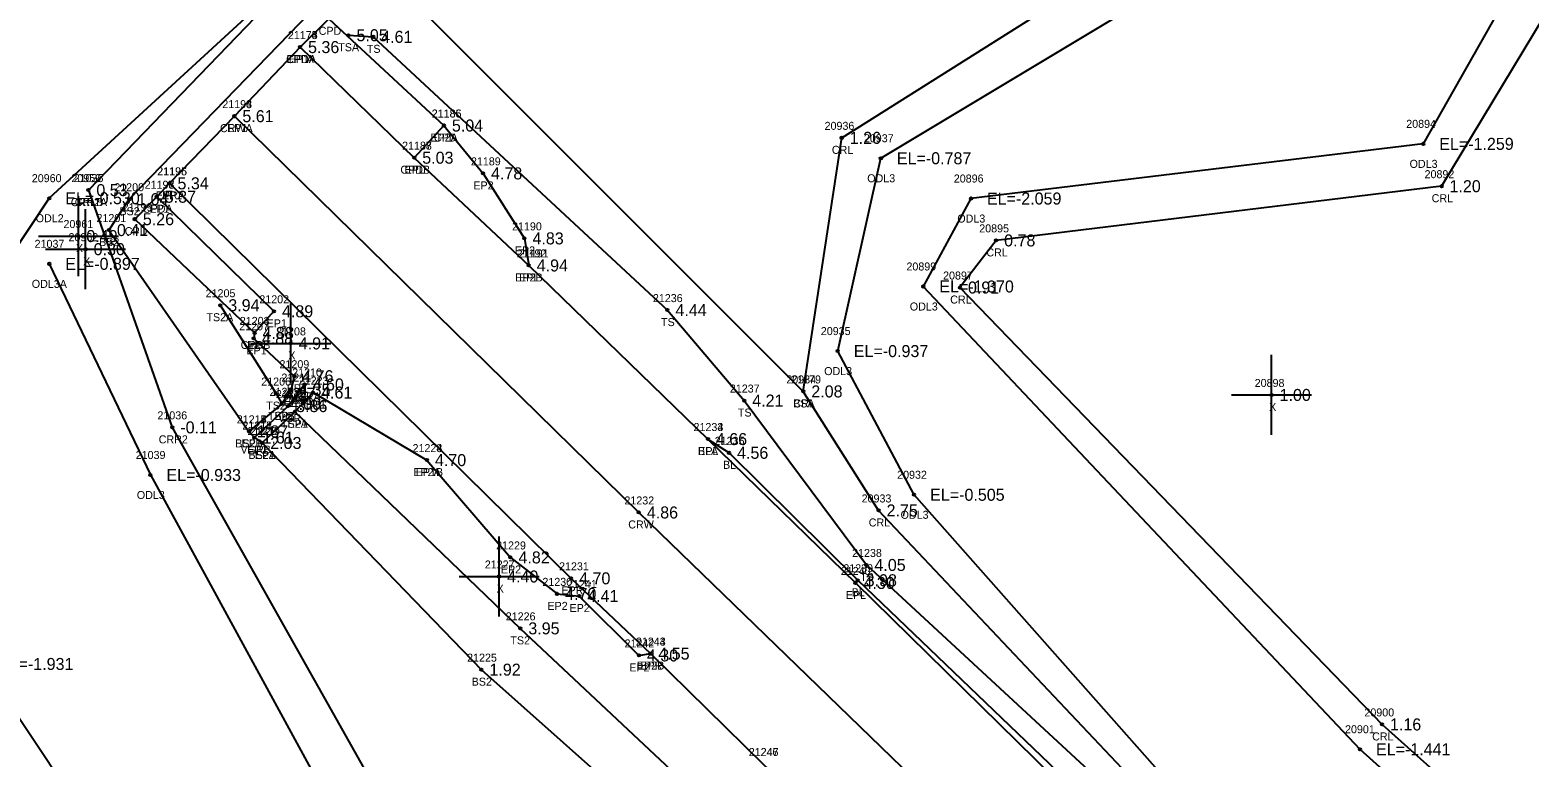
# Model space of a CAD drawing. Extents: x 2608745 to 2610333, y 641917 to 643463.
# Drawn here: x 2609542.9 to 2609730.2, y 642567.4 to 642658.2 of the extents above; entities that cross this region are included whole.
import ezdxf

# ---------------------------------------------------------------- set-up
doc = ezdxf.new("R2010")
doc.units = 0
for name, color, linetype in [('RD_DTM_BkLn1', 7, 'Continuous'), ('RD_DTM_BkLn2', 7, 'Continuous'), ('RD_DTM_BkLn_txCode', 7, 'Continuous'), ('RD_EX_Conc', 7, 'Continuous'), ('RD_EX_Conc_txCode', 7, 'Continuous'), ('RD_EX_H2O', 7, 'Continuous'), ('RD_EX_H2O_txCode', 7, 'Continuous'), ('RD_EX_Misc', 7, 'Continuous'), ('RD_EX_Misc_txCode', 7, 'Continuous'), ('RD_EX_Road', 7, 'Continuous'), ('RD_EX_Road_txCode', 7, 'Continuous'), ('RD_EX_TX_Conc_ELEV', 7, 'Continuous'), ('RD_EX_TX_H2O_ELEV', 7, 'Continuous'), ('RD_EX_TX_Misc_ELEV', 7, 'Continuous'), ('RD_EX_TX_Road_ELEV', 7, 'Continuous'), ('RD_HC_Survey_ELEV', 7, 'Continuous'), ('RD_HC_Survey_txCode', 7, 'Continuous'), ('RD_SMD_Locator', 7, 'Continuous')]:
    doc.layers.add(name, color=color, linetype=linetype)

msp = doc.modelspace()

# ---------------------------------------------------------------- linework, layer by layer
at = {"layer": 'RD_DTM_BkLn1'}
for points in [[(2609568.4, 642647.43), (2609618.95, 642597.92), (2609693.89, 642525.38), (2609771.33, 642450.27), (2609850.26, 642373.69), (2609929.54, 642297.24), (2610000.01, 642230.49), (2610078.71, 642154.75), (2610156.09, 642080.44), (2610235.53, 642002.94), (2610263.59, 641975.77)], [(2609627.58, 642607.09), (2609630.23, 642605.37), (2609646.31, 642589.45), (2609703.16, 642535.02), (2609781.51, 642459.84), (2609859.44, 642383.51), (2609938.95, 642307.03), (2610008.76, 642239.49), (2610086.74, 642162.99), (2610105.31, 642145.89), (2610105.31, 642145.89), (2610140.26, 642113.1), (2610153.89, 642100.28), (2610164.72, 642089.82), (2610189.2, 642065.46)]]:
    msp.add_lwpolyline(points, dxfattribs=at)
at = {"layer": 'RD_DTM_BkLn2'}
msp.add_line((2609639.51, 642613.04), (2609586.16, 642666.36), dxfattribs=at)
for points in [[(2609586.16, 642666.36), (2609582.27, 642665.19), (2609577.87, 642660.38), (2609555.26, 642637.05), (2609552.72, 642633.2), (2609570.22, 642608.05)], [(2609582.66, 642657.54), (2609585.75, 642657.34), (2609622.53, 642623.2), (2609632.13, 642611.9), (2609647.4, 642591.36), (2609682.93, 642558.52), (2609706.14, 642537.77), (2609755.54, 642496.98), (2609786.05, 642464.88), (2609864.24, 642388.44), (2609941.53, 642310.67), (2610012.94, 642244.46), (2610082.83, 642179.18), (2610093.52, 642170.29)], [(2609566.64, 642623.81), (2609573.62, 642612.77), (2609574.32, 642611.49)], [(2609575.96, 642610.5), (2609604.14, 642583.44), (2609629.67, 642559.46), (2609643.02, 642545.36), (2609646.06, 642538.31)], [(2609571.88, 642606.6), (2609599.28, 642578.28), (2609624.62, 642555.74), (2609639.66, 642545.5), (2609646.06, 642538.31)]]:
    msp.add_lwpolyline(points, dxfattribs=at)
at = {"layer": 'RD_EX_Conc'}
for points in [[(2609576.61, 642656.06), (2609580.19, 642659.59), (2609594.59, 642646.26), (2609590.88, 642642.24)], [(2609558.7, 642637.36), (2609555.96, 642634.56), (2609570.92, 642620.35)]]:
    msp.add_lwpolyline(points, dxfattribs=at)
at = {"layer": 'RD_EX_H2O'}
for points in [[(2609940.72, 642981.52), (2609865.8, 642912.86), (2609792.29, 642852.87), (2609723.77, 642786.36), (2609663.25, 642717.18), (2609610.37, 642689.46), (2609581.45, 642670.47), (2609545.26, 642637.18), (2609509.19, 642582.86), (2609482.73, 642569.2), (2609408.72, 642506.3), (2609370.25, 642508.5), (2609327.7, 642455.81), (2609283.83, 642369.21), (2609262.12, 642251.22)], [(2609943.79, 642976.05), (2609869.55, 642907.14), (2609797.73, 642847.7), (2609725.24, 642780.75), (2609667.97, 642714.2), (2609673.28, 642700.22), (2609713.56, 642689.91), (2609733.33, 642661.98), (2609719.28, 642638.68), (2609663.61, 642631.91), (2609659.09, 642626.02), (2609711.84, 642571.44), (2609760.21, 642528.21), (2609792.62, 642516.23), (2609800.76, 642528.12), (2609797.45, 642563.99), (2609816.12, 642605.87)], [(2609662.06, 642711.74), (2609667.71, 642698.47), (2609710.28, 642682.9), (2609727.91, 642663.26), (2609716.99, 642643.97), (2609660.46, 642637.14), (2609654.51, 642626.15), (2609709.09, 642568.34), (2609756.97, 642525.37), (2609791.92, 642510.53), (2609803.29, 642524.08), (2609799.58, 642559.74), (2609817.68, 642600.07)], [(2609827.02, 642593.77), (2609813.83, 642563.83), (2609821.87, 642523.17), (2609816.05, 642503.71), (2609776.93, 642503.96), (2609742.39, 642528.68), (2609685.39, 642563.92), (2609653.36, 642600.13), (2609643.82, 642618.08), (2609649.2, 642642.17), (2609682.55, 642662.2), (2609681.94, 642669.7), (2609650.34, 642688.25), (2609625.49, 642693.15)], [(2609830.46, 642590.52), (2609816.18, 642559.99), (2609824.93, 642525.1), (2609819.57, 642500.66), (2609777.53, 642499.54), (2609740.45, 642527.35), (2609685.03, 642559.92), (2609648.92, 642598.17), (2609639.51, 642613.04), (2609644.31, 642644.72), (2609677.66, 642665.76), (2609646.17, 642685.39), (2609611.73, 642684.8), (2609586.16, 642666.36), (2609575.62, 642664.58), (2609550.15, 642638.19)], [(2609550.15, 642638.19), (2609560.64, 642608.55), (2609596.58, 642544.67), (2609665.26, 642493.63), (2609726.89, 642435.57), (2609728.97, 642442.01), (2609745.88, 642433.78), (2609753.45, 642414.77), (2609764.24, 642411.87), (2609765.65, 642391.82), (2609764.35, 642384.35), (2609816.5, 642340.65), (2609898.67, 642278.63), (2609932.36, 642236.09), (2609918.8, 642192.33)], [(2609545.26, 642628.98), (2609557.91, 642602.6), (2609591.74, 642540.6), (2609658.48, 642494.06), (2609739.9, 642422.86), (2609760.07, 642378.85), (2609808.54, 642339.07), (2609896.37, 642269.89), (2609925.48, 642240.69), (2609915.11, 642188.91), (2609891.33, 642158.21), (2609835.84, 642063.03)], [(2609518.22, 642586.65), (2609536.97, 642578.99), (2609575.62, 642520.95), (2609643.94, 642461.12), (2609713.29, 642393.38), (2609797.14, 642314.29), (2609845.08, 642297.38), (2609901.61, 642240.2), (2609849.12, 642177.48), (2609793.89, 642090.6)]]:
    msp.add_lwpolyline(points, dxfattribs=at)
at = {"layer": 'RD_EX_Misc'}
for p, q in [((2609548.9, 642627.45), (2609548.9, 642637.45)), ((2609549.81, 642625.81), (2609549.81, 642635.81)), ((2609543.9, 642632.45), (2609553.9, 642632.45)), ((2609544.81, 642630.81), (2609554.81, 642630.81)), ((2609575.45, 642614.04), (2609575.45, 642624.04)), ((2609570.45, 642619.04), (2609580.45, 642619.04)), ((2609698.04, 642607.6), (2609698.04, 642617.6)), ((2609693.04, 642612.6), (2609703.04, 642612.6)), ((2609601.49, 642584.92), (2609601.49, 642594.92)), ((2609596.49, 642589.92), (2609606.49, 642589.92))]:
    msp.add_line(p, q, dxfattribs=at)
at = {"layer": 'RD_EX_Road'}
for points in [[(2609576.61, 642656.06), (2609568.4, 642647.43), (2609560.29, 642639.04), (2609558.7, 642637.36), (2609573.35, 642623.05), (2609570.92, 642620.35), (2609570.83, 642619.67), (2609575.88, 642614.94), (2609575.51, 642613.27), (2609574.32, 642611.49), (2609570.22, 642608.05), (2609570.91, 642607.28), (2609571.88, 642606.6), (2609575.96, 642610.5), (2609578.24, 642612.9), (2609592.47, 642604.46)], [(2609576.61, 642656.06), (2609590.88, 642642.24), (2609605.19, 642628.78), (2609627.58, 642607.09), (2609646.03, 642589.11), (2609702.18, 642534.04), (2609780.35, 642458.95), (2609858.79, 642382.83), (2609938.32, 642306.42), (2610008.62, 642239.32), (2610086.3, 642162.54), (2610164.18, 642089.49), (2610189.2, 642065.46), (2610214.78, 642040.19), (2610225.86, 642030.16), (2610226.32, 642028.39), (2610235.43, 642019.75), (2610260.23, 641995.63), (2610272.39, 641983.25)], [(2609594.59, 642646.26), (2609599.48, 642640.28), (2609604.66, 642632.16), (2609605.19, 642628.78)], [(2609560.29, 642639.04), (2609610.49, 642589.69), (2609620.39, 642580.29), (2609634.49, 642566.49), (2609647.6, 642554.19), (2609656.49, 642545.43), (2609683.33, 642519.48), (2609697.84, 642505.38), (2609722.29, 642481.47), (2609722.29, 642481.47), (2609722.29, 642481.47), (2609762.93, 642442.03), (2609781.47, 642423.77), (2609797.04, 642408.62), (2609841.8, 642365.54), (2609898.22, 642311.07)], [(2609577.18, 642613.91), (2609575.12, 642611.21), (2609570.91, 642607.28)], [(2609592.47, 642604.46), (2609602.91, 642592.3), (2609608.74, 642587.75), (2609611.5, 642587.48), (2609618.96, 642580.06), (2609620.39, 642580.29)]]:
    msp.add_lwpolyline(points, dxfattribs=at)
at = {"layer": 'RD_SMD_Locator'}
for centre in [(2609582.66, 642657.54), (2609585.75, 642657.34), (2609576.61, 642656.06), (2609576.61, 642656.06), (2609576.61, 642656.06), (2609568.4, 642647.43), (2609568.4, 642647.43), (2609594.59, 642646.26), (2609594.59, 642646.26), (2609644.31, 642644.72), (2609716.99, 642643.97), (2609590.88, 642642.24), (2609590.88, 642642.24), (2609649.2, 642642.17), (2609599.48, 642640.28), (2609550.15, 642638.19), (2609550.15, 642638.19), (2609560.29, 642639.04), (2609560.29, 642639.04), (2609719.28, 642638.68), (2609545.26, 642637.18), (2609555.26, 642637.05), (2609558.7, 642637.36), (2609558.7, 642637.36), (2609660.46, 642637.14), (2609555.96, 642634.56), (2609552.72, 642633.2), (2609548.9, 642632.45), (2609549.81, 642630.81), (2609604.66, 642632.16), (2609663.61, 642631.91), (2609545.26, 642628.98), (2609605.19, 642628.78), (2609605.19, 642628.78), (2609654.51, 642626.15), (2609659.09, 642626.02), (2609566.64, 642623.81), (2609622.53, 642623.2), (2609573.35, 642623.05), (2609570.83, 642619.67), (2609570.92, 642620.35), (2609570.92, 642620.35), (2609575.45, 642619.04), (2609643.82, 642618.08), (2609575.88, 642614.94), (2609577.18, 642613.91), (2609573.62, 642612.77), (2609575.51, 642613.27), (2609578.24, 642612.9), (2609639.51, 642613.04), (2609639.51, 642613.04), (2609698.04, 642612.6), (2609574.32, 642611.49), (2609574.32, 642611.49), (2609575.12, 642611.21), (2609575.96, 642610.5), (2609575.96, 642610.5), (2609632.13, 642611.9), (2609560.64, 642608.55), (2609570.22, 642608.05), (2609570.22, 642608.05), (2609570.91, 642607.28), (2609570.91, 642607.28), (2609571.88, 642606.6), (2609571.88, 642606.6), (2609627.58, 642607.09), (2609627.58, 642607.09), (2609592.47, 642604.46), (2609592.47, 642604.46), (2609630.23, 642605.37), (2609557.91, 642602.6), (2609653.36, 642600.13), (2609618.95, 642597.92), (2609648.92, 642598.17), (2609602.91, 642592.3), (2609647.4, 642591.36), (2609601.49, 642589.92), (2609610.49, 642589.69), (2609608.74, 642587.75), (2609646.03, 642589.11), (2609646.31, 642589.45), (2609611.5, 642587.48), (2609604.14, 642583.44), (2609620.39, 642580.29), (2609620.39, 642580.29), (2609599.28, 642578.28), (2609618.96, 642580.06), (2609711.84, 642571.44), (2609709.09, 642568.34)]:
    msp.add_circle(centre, 0.15, dxfattribs=at)

# ---------------------------------------------------------------- texts
at = {"layer": 'RD_DTM_BkLn_txCode'}
for s, p in [('TSA', (2609581.38, 642655.54)), ('TS', (2609584.95, 642655.34)), ('21200', (2609553.39, 642638.05)), ('21201', (2609551.17, 642634.2)), ('BS2', (2609554.03, 642635.05)), ('BS2', (2609551.49, 642631.2)), ('21205', (2609564.81, 642624.81)), ('21236', (2609620.71, 642624.2)), ('TS2A', (2609564.91, 642621.81)), ('TS', (2609621.73, 642621.2)), ('21206', (2609571.76, 642613.77)), ('21179', (2609638, 642614.04)), ('21213', (2609572.8, 642612.49)), ('21222', (2609574.17, 642611.5)), ('21237', (2609630.33, 642612.9)), ('TS2', (2609572.38, 642610.77)), ('TS2B', (2609572.6, 642609.49)), ('TS', (2609631.33, 642609.9)), ('BSA', (2609638.24, 642611.04)), ('21215', (2609568.7, 642609.05)), ('21220', (2609570.04, 642607.6)), ('TS2A', (2609574.23, 642608.5)), ('21234', (2609625.79, 642608.09)), ('BS2B', (2609568.51, 642606.05)), ('21235', (2609628.44, 642606.37)), ('BS2A', (2609570.16, 642604.6)), ('BLA', (2609626.34, 642605.09)), ('BL', (2609629.48, 642603.37)), ('21238', (2609645.61, 642592.36)), ('21239', (2609644.51, 642590.45)), ('TS', (2609646.61, 642589.36)), ('BL', (2609645.55, 642587.45)), ('21226', (2609602.32, 642584.44)), ('TS2', (2609602.9, 642581.44)), ('21225', (2609597.49, 642579.28)), ('BS2', (2609598.06, 642576.28))]:
    msp.add_text(s, height=1, dxfattribs=at).set_placement(p)
at = {"layer": 'RD_EX_Conc_txCode'}
for s, p in [('21174', (2609575.09, 642657.06)), ('CPD', (2609578.94, 642657.59)), ('CPDA', (2609574.87, 642654.06)), ('21185', (2609593.08, 642647.26)), ('21187', (2609589.36, 642643.24)), ('CPD', (2609593.34, 642644.26)), ('CPDB', (2609589.15, 642640.24)), ('21198', (2609557.19, 642638.36)), ('21199', (2609554.44, 642635.56)), ('CPDA', (2609556.96, 642635.36)), ('CPD', (2609554.7, 642632.56)), ('21204', (2609569.08, 642621.35)), ('CPDB', (2609569.19, 642618.35))]:
    msp.add_text(s, height=1, dxfattribs=at).set_placement(p)
at = {"layer": 'RD_EX_H2O_txCode'}
for s, p in [('20936', (2609642.17, 642645.72)), ('20894', (2609714.87, 642645.97)), ('20937', (2609647.08, 642644.17)), ('CRL', (2609643.08, 642642.72)), ('20959', (2609548.03, 642639.19)), ('21035', (2609548.31, 642639.19)), ('ODL3', (2609715.29, 642640.97)), ('20892', (2609717.16, 642639.68)), ('20960', (2609543.08, 642639.18)), ('ODL3', (2609647.5, 642639.17)), ('20896', (2609658.32, 642639.14)), ('CRR2A', (2609547.96, 642636.19)), ('CRLB', (2609548.45, 642636.19)), ('CRL', (2609718.05, 642636.68)), ('ODL2', (2609543.57, 642634.18)), ('ODL3', (2609658.76, 642634.14)), ('20895', (2609661.5, 642632.91)), ('21037', (2609543.43, 642630.98)), ('CRL', (2609662.39, 642629.91)), ('20899', (2609652.4, 642628.15)), ('20897', (2609656.98, 642627.02)), ('ODL3A', (2609543.08, 642625.98)), ('ODL3', (2609652.82, 642623.15)), ('CRL', (2609657.87, 642624.02)), ('20935', (2609641.7, 642620.08)), ('ODL3', (2609642.12, 642615.08)), ('20934', (2609637.39, 642614.04)), ('21036', (2609558.78, 642609.55)), ('CRL', (2609638.28, 642611.04)), ('CRR2', (2609558.94, 642606.55)), ('21039', (2609556.07, 642604.6)), ('20932', (2609651.24, 642602.13)), ('ODL3', (2609556.21, 642599.6)), ('20933', (2609646.8, 642599.17)), ('CRL', (2609647.69, 642596.17)), ('ODL3', (2609651.67, 642597.13)), ('20900', (2609709.64, 642572.44)), ('20901', (2609707.22, 642570.34)), ('CRL', (2609710.61, 642569.44))]:
    msp.add_text(s, height=1, dxfattribs=at).set_placement(p)
at = {"layer": 'RD_EX_Misc_txCode'}
for s, p in [('20961', (2609547.04, 642633.45)), ('20962', (2609547.67, 642631.81)), ('X', (2609548.59, 642630.45)), ('X', (2609549.5, 642628.81)), ('21208', (2609573.62, 642620.04)), ('X', (2609575.14, 642617.04)), ('20898', (2609695.93, 642613.6)), ('X', (2609697.73, 642610.6)), ('21227', (2609599.7, 642590.92)), ('X', (2609601.18, 642587.92))]:
    msp.add_text(s, height=1, dxfattribs=at).set_placement(p)
at = {"layer": 'RD_EX_Road_txCode'}
for s, p in [('21173', (2609575.09, 642657.06)), ('21175', (2609575.09, 642657.06)), ('EPLA', (2609574.91, 642654.06)), ('EP1A', (2609575.2, 642654.06)), ('21193', (2609566.89, 642648.43)), ('21186', (2609593.06, 642647.26)), ('EP1', (2609567.48, 642645.43)), ('21188', (2609589.36, 642643.24)), ('EP2A', (2609592.9, 642644.26)), ('21189', (2609597.97, 642641.28)), ('21196', (2609558.75, 642640.04)), ('21195', (2609558.77, 642640.04)), ('EPL', (2609589.67, 642640.24)), ('21197', (2609557.19, 642638.36)), ('EP2', (2609598.27, 642638.28)), ('EPRA', (2609558.57, 642637.04)), ('EP1', (2609559.36, 642637.04)), ('EP1', (2609557.78, 642635.36)), ('21190', (2609603.11, 642633.16)), ('EP2', (2609603.46, 642630.16)), ('21192', (2609603.68, 642629.78)), ('21191', (2609603.96, 642629.78)), ('EP2B', (2609603.51, 642626.78)), ('EPL', (2609603.98, 642626.78)), ('21202', (2609571.52, 642624.05)), ('21207', (2609569, 642620.67)), ('21203', (2609569.08, 642621.35)), ('EP1', (2609572.43, 642621.05)), ('EP1', (2609569.91, 642617.67)), ('EP1', (2609570, 642618.35)), ('21209', (2609574.04, 642615.94)), ('21210', (2609575.63, 642614.91)), ('21211', (2609574.28, 642614.27)), ('21223', (2609576.45, 642613.9)), ('21212', (2609572.8, 642612.49)), ('21216', (2609573.59, 642612.21)), ('21221', (2609574.45, 642611.5)), ('EP1', (2609574.59, 642611.27)), ('EP1', (2609574.95, 642612.94)), ('VGRA', (2609575.42, 642611.91)), ('EP1', (2609573.4, 642609.49)), ('EP1', (2609577.32, 642610.9)), ('21214', (2609568.7, 642609.05)), ('21217', (2609569.4, 642608.28)), ('21218', (2609569.4, 642608.28)), ('21219', (2609570.36, 642607.6)), ('VGR', (2609573.86, 642609.21)), ('EP1', (2609575.04, 642608.5)), ('21233', (2609625.79, 642608.09)), ('EP1', (2609569.29, 642606.05)), ('VGRB', (2609569.17, 642605.28)), ('EP1', (2609569.99, 642605.28)), ('EP1', (2609570.96, 642604.6)), ('21224', (2609590.67, 642605.46)), ('21228', (2609590.67, 642605.46)), ('EPL', (2609626.38, 642605.09)), ('EP2A', (2609590.77, 642602.46)), ('EP1B', (2609591.07, 642602.46)), ('21229', (2609601.12, 642593.3)), ('21231', (2609608.98, 642590.69)), ('EP2', (2609601.71, 642590.3)), ('21230', (2609606.9, 642588.75)), ('21240', (2609644.2, 642590.11)), ('EPR', (2609609.27, 642587.69)), ('21241', (2609609.98, 642588.48)), ('EPL', (2609644.83, 642587.11)), ('EP2', (2609607.53, 642585.75)), ('EP2', (2609610.29, 642585.48)), ('21243', (2609618.59, 642581.29)), ('21244', (2609618.59, 642581.29)), ('21242', (2609617.17, 642581.06)), ('EP2', (2609617.76, 642578.06)), ('EP2B', (2609618.71, 642578.29)), ('EPR', (2609619.16, 642578.29)), ('21246', (2609632.68, 642567.49)), ('21247', (2609632.7, 642567.49))]:
    msp.add_text(s, height=1, dxfattribs=at).set_placement(p)
at = {"layer": 'RD_EX_TX_Conc_ELEV'}
for s, p in [('5.36', (2609577.61, 642655.31)), ('5.04', (2609595.59, 642645.51)), ('5.03', (2609591.88, 642641.49)), ('5.37', (2609559.7, 642636.61)), ('5.26', (2609556.96, 642633.81)), ('4.88', (2609571.92, 642619.6))]:
    msp.add_text(s, height=1.5, dxfattribs=at).set_placement(p)
at = {"layer": 'RD_EX_TX_H2O_ELEV'}
for s, p in [('1.26', (2609645.31, 642643.97)), ('EL=-1.259', (2609718.99, 642643.22)), ('EL=-0.787', (2609651.2, 642641.42)), ('0.53', (2609551.15, 642637.44)), ('0.53', (2609551.15, 642637.44)), ('1.20', (2609720.28, 642637.93)), ('EL=-0.530', (2609547.26, 642636.43)), ('EL=-2.059', (2609662.46, 642636.39)), ('0.78', (2609664.61, 642631.16)), ('EL=-0.897', (2609547.26, 642628.23)), ('EL=-1.370', (2609656.51, 642625.4)), ('0.91', (2609660.09, 642625.27)), ('EL=-0.937', (2609645.82, 642617.33)), ('2.08', (2609640.51, 642612.29)), ('-0.11', (2609561.64, 642607.8)), ('EL=-0.933', (2609559.91, 642601.85)), ('EL=-0.505', (2609655.36, 642599.38)), ('2.75', (2609649.92, 642597.42)), ('EL=-1.931', (2609538.97, 642578.24)), ('1.16', (2609712.84, 642570.69)), ('EL=-1.441', (2609711.09, 642567.59))]:
    msp.add_text(s, height=1.5, dxfattribs=at).set_placement(p)
at = {"layer": 'RD_EX_TX_Misc_ELEV'}
for s, p in [('5.05', (2609583.66, 642656.79)), ('4.61', (2609586.75, 642656.59)), ('1.04', (2609556.26, 642636.3)), ('0.49', (2609549.9, 642631.7)), ('0.41', (2609553.72, 642632.45)), ('0.30', (2609550.81, 642630.06)), ('3.94', (2609567.64, 642623.06)), ('4.44', (2609623.53, 642622.45)), ('4.91', (2609576.45, 642618.29)), ('4.27', (2609574.62, 642612.02)), ('4.00', (2609575.32, 642610.74)), ('4.21', (2609633.13, 642611.15)), ('2.08', (2609640.51, 642612.29)), ('1.00', (2609699.04, 642611.85)), ('4.04', (2609576.96, 642609.75)), ('1.87', (2609571.22, 642607.3)), ('2.03', (2609572.88, 642605.85)), ('4.66', (2609628.58, 642606.34)), ('4.56', (2609631.23, 642604.62)), ('4.05', (2609648.4, 642590.61)), ('4.40', (2609602.49, 642589.17)), ('3.98', (2609647.31, 642588.7)), ('3.95', (2609605.14, 642582.69)), ('1.92', (2609600.28, 642577.53))]:
    msp.add_text(s, height=1.5, dxfattribs=at).set_placement(p)
at = {"layer": 'RD_EX_TX_Road_ELEV'}
for s, p in [('5.36', (2609577.61, 642655.31)), ('5.36', (2609577.61, 642655.31)), ('5.61', (2609569.4, 642646.68)), ('5.04', (2609595.59, 642645.51)), ('5.03', (2609591.88, 642641.49)), ('4.78', (2609600.48, 642639.53)), ('5.34', (2609561.29, 642638.29)), ('5.34', (2609561.29, 642638.29)), ('5.37', (2609559.7, 642636.61)), ('4.83', (2609605.66, 642631.41)), ('4.94', (2609606.19, 642628.03)), ('4.94', (2609606.19, 642628.03)), ('4.89', (2609574.35, 642622.3)), ('4.88', (2609571.83, 642618.92)), ('4.88', (2609571.92, 642619.6)), ('4.35', (2609576.51, 642612.52)), ('4.76', (2609576.88, 642614.19)), ('4.60', (2609578.18, 642613.16)), ('4.00', (2609575.32, 642610.74)), ('4.61', (2609579.24, 642612.15)), ('3.86', (2609576.12, 642610.46)), ('4.04', (2609576.96, 642609.75)), ('1.87', (2609571.22, 642607.3)), ('1.61', (2609571.91, 642606.53)), ('1.61', (2609571.91, 642606.53)), ('2.03', (2609572.88, 642605.85)), ('4.66', (2609628.58, 642606.34)), ('4.70', (2609593.47, 642603.71)), ('4.70', (2609593.47, 642603.71)), ('4.82', (2609603.91, 642591.55)), ('4.70', (2609611.49, 642588.94)), ('4.30', (2609647.03, 642588.36)), ('4.70', (2609609.74, 642587)), ('4.41', (2609612.5, 642586.73)), ('4.30', (2609619.96, 642579.31)), ('4.55', (2609621.39, 642579.54)), ('4.55', (2609621.39, 642579.54))]:
    msp.add_text(s, height=1.5, dxfattribs=at).set_placement(p)
at = {"layer": 'RD_HC_Survey_ELEV'}
for s, p in [('5.61', (2609569.4, 642646.68)), ('4.86', (2609619.95, 642597.17))]:
    msp.add_text(s, height=1.5, dxfattribs=at).set_placement(p)
at = {"layer": 'RD_HC_Survey_txCode'}
for s, p in [('21194', (2609566.89, 642648.43)), ('CRWA', (2609566.6, 642645.43)), ('21232', (2609617.15, 642598.92)), ('CRW', (2609617.63, 642595.92))]:
    msp.add_text(s, height=1, dxfattribs=at).set_placement(p)

doc.saveas('drawing.dxf')
